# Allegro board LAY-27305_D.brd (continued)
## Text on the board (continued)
L2_GND_1: 2 OF 12 | GROUND PLANE 1
L3_PWR_1: 3 OF 12 | POWER PLANE 1
L4_PWR_2: 4 OF 12 | POWER PLANE 2
L5_GND_2: 5 OF 12 | GROUND PLANE 2
DIMENSION: PRIMARY DATUM | GRID ORIGIN | VIEW FROM PRIMARY SIDE
DISPLAY_TOP: 45  +/- 15 | 21. V-SCORE MUST BE IMPLEMENTED TO CUT THOSE LITTLE BOARDS. DIMENSIONS PROVIDED IN DETAIL C. | 22 | THESE THROUGH HOLES MUST GO THROUGH ELECTRODE FOOTPRINT. | 8 | 15 | 16 | 21 | LAYER | L6_SS | L1_PS | SINGLE ENDED(50 OHMS) | 8.00 | LINE WIDTH | V-SCORE | DETAIL C | 9.00 | DETAIL B | CONTROLLED IMPEDANCE TABLE | DIFFERENTIAL (90 OHMS) | TOP OF PCB | BOTTOM OF PCB | 7.00 | SPACE (AIR GAP) | (50 OHMS) | 18.00 | RF SIGNAL
User.5: 8 OF 12 | PRIMARY SOLDER PASTE
User.6: 11 OF 12 | SECONDARY SOLDER PASTE
User.29: FIGURE | SIZE | 8.0 | 36.0 | 40.0 | 50.0 | 28.0 | 39.0 | 125.0 | DRILL CHART: TOP to BOTTOM | ALL UNITS ARE IN MILS | TOLERANCE | +0.0/-8.0 | +3.0/-3.0 | +2.0/-2.0 | +4.0/-4.0 | PLATED | NON-PLATED | QTY | 683 | 4 | 6 | 2 | 3 | 24
User.30: FIGURE | SIZE | ALL UNITS ARE IN MILS | TOLERANCE | PLATED | QTY
